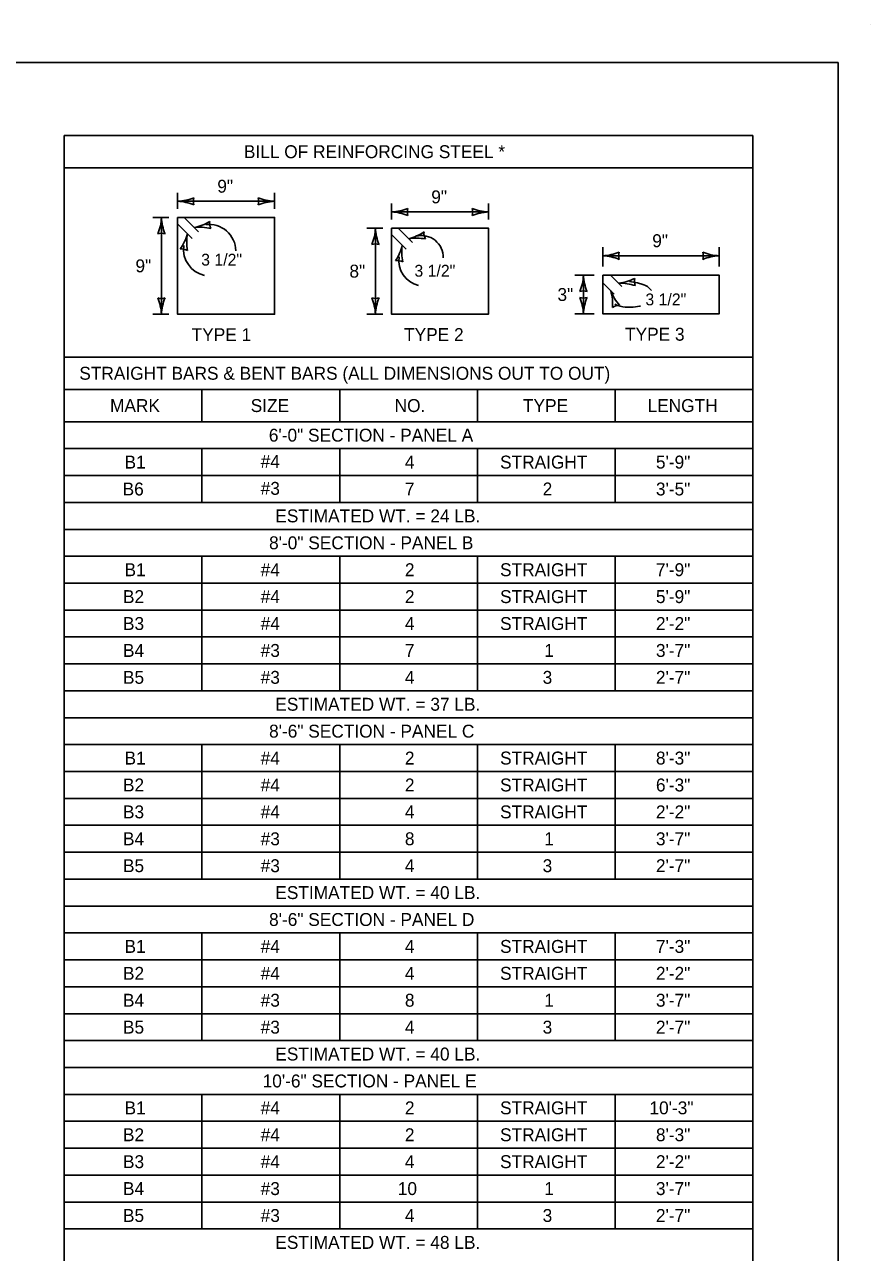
# Model space of a CAD drawing. Extents: x 49991.4 to 50021, y 49987.6 to 50011.4.
# Drawn here: x 50012.97 to 50016.9, y 49993.47 to 49999.18 of the extents above; entities that cross this region are included whole.
import ezdxf

# ---------------------------------------------------------------- set-up
doc = ezdxf.new("R2010")
doc.units = 0
for name, color, linetype in [('Level 1', 7, 'Continuous'), ('Level 2', 7, 'Continuous'), ('Level 3', 7, 'Continuous')]:
    doc.layers.add(name, color=color, linetype=linetype)

msp = doc.modelspace()

# ---------------------------------------------------------------- linework, layer by layer
at = {"layer": 'Level 1'}
for p, q in [((50016.9001, 49999.1756), (50016.9001, 49999.1756)), ((50013.713, 49998.2795), (50013.7802, 49998.2124)), ((50013.683, 49998.2495), (50013.7502, 49998.1824)), ((50014.7066, 49998.23), (50014.7738, 49998.1629)), ((50014.6766, 49998.2), (50014.7438, 49998.1329)), ((50015.6936, 49998.0114), (50015.7458, 49997.9592)), ((50015.6576, 49997.9754), (50015.7098, 49997.9232))]:
    msp.add_line(p, q, dxfattribs=at)
for points in [[(49999.3835, 49998.9992), (50016.7501, 49998.9992), (50016.7501, 49987.7988), (49999.3835, 49987.7988)], [(50013.683, 49998.2795), (50014.133, 49998.2795), (50014.133, 49997.8295), (50013.683, 49997.8295)], [(50014.6766, 49998.23), (50015.1266, 49998.23), (50015.1266, 49997.8299), (50014.6766, 49997.8299)], [(50015.6576, 49998.0114), (50016.1976, 49998.0114), (50016.1976, 49997.8314), (50015.6576, 49997.8314)]]:
    msp.add_lwpolyline(points, close=True, dxfattribs=at)
at = {"layer": 'Level 2'}
for p, q in [((50013.1565, 49998.6599), (50016.3545, 49998.6599)), ((50013.1565, 49991.0805), (50013.1565, 49998.6599)), ((50016.3545, 49991.0805), (50016.3545, 49998.6599)), ((50013.1565, 49998.5099), (50016.3545, 49998.5099)), ((50016.3545, 49997.6305), (50013.1565, 49997.6305)), ((50016.3545, 49997.4805), (50013.1565, 49997.4805)), ((50013.7961, 49997.3305), (50013.7961, 49997.4805)), ((50014.4357, 49997.3305), (50014.4357, 49997.4805)), ((50015.0753, 49997.3305), (50015.0753, 49997.4805)), ((50015.7149, 49997.3305), (50015.7149, 49997.4805)), ((50016.3545, 49997.3305), (50013.1565, 49997.3305)), ((50016.3545, 49997.2055), (50013.1565, 49997.2055)), ((50013.7961, 49996.9555), (50013.7961, 49997.2055)), ((50014.4357, 49996.9555), (50014.4357, 49997.2055)), ((50015.0753, 49996.9555), (50015.0753, 49997.2055)), ((50015.7149, 49996.9555), (50015.7149, 49997.2055)), ((50016.3545, 49997.0805), (50013.1565, 49997.0805)), ((50016.3545, 49996.9555), (50013.1565, 49996.9555)), ((50016.3545, 49996.8305), (50013.1565, 49996.8305)), ((50016.3545, 49996.7055), (50013.1565, 49996.7055)), ((50013.7961, 49996.0805), (50013.7961, 49996.7055)), ((50014.4357, 49996.0805), (50014.4357, 49996.7055)), ((50015.0753, 49996.0805), (50015.0753, 49996.7055)), ((50015.7149, 49996.0805), (50015.7149, 49996.7055)), ((50016.3545, 49996.5805), (50013.1565, 49996.5805)), ((50016.3545, 49996.4555), (50013.1565, 49996.4555)), ((50016.3545, 49996.3305), (50013.1565, 49996.3305)), ((50016.3545, 49996.2055), (50013.1565, 49996.2055)), ((50016.3545, 49996.0805), (50013.1565, 49996.0805)), ((50016.3545, 49995.9555), (50013.1565, 49995.9555)), ((50016.3545, 49995.8305), (50013.1565, 49995.8305)), ((50013.7961, 49995.2055), (50013.7961, 49995.8305)), ((50014.4357, 49995.2055), (50014.4357, 49995.8305)), ((50015.0753, 49995.2055), (50015.0753, 49995.8305)), ((50015.7149, 49995.2055), (50015.7149, 49995.8305)), ((50016.3545, 49995.7055), (50013.1565, 49995.7055)), ((50016.3545, 49995.5805), (50013.1565, 49995.5805)), ((50016.3545, 49995.4555), (50013.1565, 49995.4555)), ((50016.3545, 49995.3305), (50013.1565, 49995.3305)), ((50016.3545, 49995.2055), (50013.1565, 49995.2055)), ((50016.3545, 49995.0805), (50013.1565, 49995.0805)), ((50016.3545, 49994.9555), (50013.1565, 49994.9555)), ((50013.7961, 49994.4555), (50013.7961, 49994.9555)), ((50014.4357, 49994.4555), (50014.4357, 49994.9555)), ((50015.0753, 49994.4555), (50015.0753, 49994.9555)), ((50015.7149, 49994.4555), (50015.7149, 49994.9555)), ((50016.3545, 49994.8305), (50013.1565, 49994.8305)), ((50016.3545, 49994.7055), (50013.1565, 49994.7055)), ((50016.3545, 49994.5805), (50013.1565, 49994.5805)), ((50016.3545, 49994.4555), (50013.1565, 49994.4555)), ((50016.3545, 49994.3305), (50013.1565, 49994.3305)), ((50016.3545, 49994.2055), (50013.1565, 49994.2055)), ((50013.7961, 49993.5805), (50013.7961, 49994.2055)), ((50014.4357, 49993.5805), (50014.4357, 49994.2055)), ((50015.0753, 49993.5805), (50015.0753, 49994.2055)), ((50015.7149, 49993.5805), (50015.7149, 49994.2055)), ((50016.3545, 49994.0805), (50013.1565, 49994.0805)), ((50016.3545, 49993.9555), (50013.1565, 49993.9555)), ((50016.3545, 49993.8305), (50013.1565, 49993.8305)), ((50016.3545, 49993.7055), (50013.1565, 49993.7055)), ((50016.3545, 49993.5805), (50013.1565, 49993.5805))]:
    msp.add_line(p, q, dxfattribs=at)
at = {"layer": 'Level 3'}
for p, q in [((50013.683, 49998.3195), (50013.683, 49998.3945)), ((50014.133, 49998.3195), (50014.133, 49998.3945)), ((50013.683, 49998.3545), (50014.133, 49998.3545)), ((50014.6766, 49998.27), (50014.6766, 49998.345)), ((50015.1266, 49998.27), (50015.1266, 49998.345)), ((50013.643, 49998.2795), (50013.568, 49998.2795)), ((50013.608, 49997.8295), (50013.608, 49998.2795)), ((50014.6766, 49998.305), (50015.1266, 49998.305)), ((50014.6366, 49998.23), (50014.5616, 49998.23)), ((50014.6016, 49997.8299), (50014.6016, 49998.23)), ((50015.6576, 49998.0514), (50015.6576, 49998.1414)), ((50015.6576, 49998.1014), (50016.1976, 49998.1014)), ((50016.1976, 49998.0514), (50016.1976, 49998.1414)), ((50015.6176, 49998.0114), (50015.5275, 49998.0114)), ((50015.5675, 49997.8314), (50015.5675, 49998.0114)), ((50013.643, 49997.8295), (50013.568, 49997.8295)), ((50014.6366, 49997.8299), (50014.5616, 49997.8299)), ((50015.6176, 49997.8314), (50015.5275, 49997.8314))]:
    msp.add_line(p, q, dxfattribs=at)
for centre, radius, start, end in [((50013.6715, 49998.5872), 0.233, 272.8273, 292.0772), ((50013.6738, 49998.1324), 0.2223, 67.456, 87.6395), ((50013.8112, 49998.3545), 0.0548, 162.1388, 197.8612), ((50014.1422, 49998.5766), 0.2223, 247.456, 267.6395), ((50014.0048, 49998.3545), 0.0548, 342.1388, 17.8612), ((50014.1445, 49998.1218), 0.233, 92.8273, 112.0772), ((50013.3859, 49998.2887), 0.2223, 337.456, 357.6395), ((50013.8407, 49998.291), 0.233, 182.8273, 202.0772), ((50014.6651, 49998.5377), 0.233, 272.8273, 292.0772), ((50014.6674, 49998.0829), 0.2223, 67.456, 87.6395), ((50014.8048, 49998.305), 0.0548, 162.1388, 197.8612), ((50015.1358, 49998.5271), 0.2223, 247.456, 267.6395), ((50014.9984, 49998.305), 0.0548, 342.1388, 17.8612), ((50015.1381, 49998.0723), 0.233, 92.8273, 112.0772), ((50013.7131, 49998.461), 0.233, 281.5629, 300.8128), ((50013.7845, 49998.0118), 0.2223, 76.1916, 96.3752), ((50013.8294, 49998.1235), 0.1237, 0.6372, 97.4281), ((50013.8865, 49998.2522), 0.0548, 170.8745, 206.5968), ((50014.3795, 49998.2392), 0.2223, 337.456, 357.6395), ((50014.8343, 49998.2415), 0.233, 182.8273, 202.0772), ((50014.6973, 49998.4059), 0.233, 284.6402, 303.8901), ((50014.8817, 49998.2068), 0.0548, 173.9517, 209.6741), ((50013.608, 49998.1513), 0.0548, 72.1388, 107.8612), ((50013.514, 49998.2616), 0.2223, 324.7688, 344.9523), ((50013.9582, 49998.164), 0.233, 170.1401, 189.39), ((50014.6016, 49998.1018), 0.0548, 72.1388, 107.8612), ((50014.7927, 49997.9612), 0.2223, 79.2689, 99.4524), ((50014.8157, 49998.0947), 0.1007, 358.0024, 104.4981), ((50013.7005, 49998.0788), 0.0548, 59.4516, 95.174), ((50013.8351, 49998.1315), 0.1245, 172.119, 257.5679), ((50014.5094, 49998.2007), 0.2223, 326.8049, 346.9884), ((50014.828, 49998.0787), 0.1178, 171.5129, 257.0556), ((50014.9569, 49998.1189), 0.233, 172.1762, 191.426), ((50015.6461, 49998.3341), 0.233, 272.8273, 292.0772), ((50015.6484, 49997.8793), 0.2223, 67.456, 87.6395), ((50015.7858, 49998.1014), 0.0548, 162.1388, 197.8612), ((50016.2068, 49998.3235), 0.2223, 247.456, 267.6395), ((50016.0694, 49998.1014), 0.0548, 342.1388, 17.8612), ((50016.2091, 49997.8687), 0.233, 92.8273, 112.0772), ((50014.7023, 49998.0246), 0.0548, 61.4877, 97.21), ((50015.3454, 49998.0206), 0.2223, 337.456, 357.6395), ((50015.8002, 49998.0229), 0.233, 182.8273, 202.0772), ((50015.7022, 49998.205), 0.233, 277.1537, 296.4036), ((50015.8591, 49997.9835), 0.0548, 166.4652, 202.1876), ((50015.5675, 49997.8832), 0.0548, 72.1388, 107.8612), ((50015.4807, 49997.8772), 0.2223, 355.8418, 16.0253), ((50015.9116, 49998.0229), 0.233, 201.2131, 220.4629), ((50015.7388, 49997.7516), 0.2223, 71.7824, 91.9659), ((50013.608, 49997.9577), 0.0548, 252.1388, 287.8612), ((50013.3753, 49997.818), 0.233, 2.8273, 22.0772), ((50013.8301, 49997.8203), 0.2223, 157.456, 177.6395), ((50014.6016, 49997.9581), 0.0548, 252.1388, 287.8612), ((50014.3689, 49997.8184), 0.233, 2.8273, 22.0772), ((50014.8237, 49997.8207), 0.2223, 157.456, 177.6395), ((50015.5675, 49997.9596), 0.0548, 252.1388, 287.8612), ((50015.3348, 49997.8199), 0.233, 2.8273, 22.0772), ((50015.7896, 49997.8222), 0.2223, 157.456, 177.6395), ((50015.7348, 49997.8169), 0.0548, 90.5246, 126.2469)]:
    msp.add_arc(centre, radius, start, end, dxfattribs=at)
for points in [[(50015.7818, 49997.9817), (50015.8184, 49997.9752), (50015.8382, 49997.9699), (50015.8719, 49997.9524), (50015.8833, 49997.9402)], [(50015.7133, 49997.8762), (50015.7267, 49997.8709), (50015.7511, 49997.8648), (50015.8275, 49997.8671), (50015.8324, 49997.8684)]]:
    msp.add_spline(points, degree=3, dxfattribs=at)

# ---------------------------------------------------------------- texts
at = {"layer": 'Level 2'}
for s, height, p in [('BILL OF REINFORCING STEEL *', 0.06, (50013.9909, 49998.5549)), ('9"', 0.06, (50013.8674, 49998.3945)), ('9"', 0.06, (50014.861, 49998.345)), ('9"', 0.06, (50015.887, 49998.1414)), ('3 1/2"', 0.055, (50013.7925, 49998.0558)), ('9"', 0.06, (50013.4873, 49998.0245)), ('8"', 0.06, (50014.4809, 49998)), ('3 1/2"', 0.055, (50014.7827, 49998.0044)), ('3"', 0.06, (50015.4468, 49997.8914)), ('3 1/2"', 0.055, (50015.8552, 49997.8712)), ('TYPE 1', 0.06, (50013.7483, 49997.705)), ('TYPE 2', 0.06, (50014.7347, 49997.7054)), ('TYPE 3', 0.06, (50015.7607, 49997.7069)), ('STRAIGHT BARS & BENT BARS (ALL DIMENSIONS OUT TO OUT)', 0.06, (50013.2267, 49997.5255)), ('MARK', 0.06, (50013.3693, 49997.3755)), ('SIZE', 0.06, (50014.0224, 49997.3755)), ('NO.', 0.06, (50014.6907, 49997.3755)), ('TYPE', 0.06, (50015.2867, 49997.3755)), ('LENGTH', 0.06, (50015.8651, 49997.3755)), ('6\'-0" SECTION - PANEL A', 0.06, (50014.1067, 49997.238)), ('B1', 0.06, (50013.4367, 49997.113)), ('#4', 0.06, (50014.0689, 49997.116)), ('4', 0.06, (50014.7385, 49997.113)), ('STRAIGHT', 0.06, (50015.1804, 49997.113)), ('5\'-9"', 0.06, (50015.9041, 49997.113)), ('B6', 0.06, (50013.4277, 49996.988)), ('#3', 0.06, (50014.0689, 49996.991)), ('7', 0.06, (50014.7385, 49996.988)), ('2', 0.06, (50015.3781, 49996.988)), ('3\'-5"', 0.06, (50015.9041, 49996.988)), ('ESTIMATED WT. = 24 LB.', 0.06, (50014.1367, 49996.863)), ('8\'-0" SECTION - PANEL B', 0.06, (50014.1077, 49996.738)), ('B1', 0.06, (50013.4367, 49996.613)), ('#4', 0.06, (50014.0689, 49996.613)), ('2', 0.06, (50014.7385, 49996.613)), ('STRAIGHT', 0.06, (50015.1804, 49996.613)), ('7\'-9"', 0.06, (50015.9041, 49996.613)), ('B2', 0.06, (50013.4293, 49996.488)), ('#4', 0.06, (50014.0689, 49996.488)), ('2', 0.06, (50014.7385, 49996.488)), ('STRAIGHT', 0.06, (50015.1804, 49996.488)), ('5\'-9"', 0.06, (50015.9041, 49996.488)), ('B3', 0.06, (50013.4293, 49996.363)), ('#4', 0.06, (50014.0689, 49996.363)), ('4', 0.06, (50014.7385, 49996.363)), ('STRAIGHT', 0.06, (50015.1804, 49996.363)), ('2\'-2"', 0.06, (50015.9041, 49996.363)), ('B4', 0.06, (50013.4293, 49996.238)), ('#3', 0.06, (50014.0689, 49996.238)), ('7', 0.06, (50014.7385, 49996.238)), ('1', 0.06, (50015.3855, 49996.238)), ('3\'-7"', 0.06, (50015.9041, 49996.238)), ('B5', 0.06, (50013.4293, 49996.113)), ('#3', 0.06, (50014.0689, 49996.113)), ('4', 0.06, (50014.7385, 49996.113)), ('3', 0.06, (50015.3781, 49996.113)), ('2\'-7"', 0.06, (50015.9041, 49996.113)), ('ESTIMATED WT. = 37 LB.', 0.06, (50014.1367, 49995.988)), ('8\'-6" SECTION - PANEL C', 0.06, (50014.1077, 49995.863)), ('B1', 0.06, (50013.4367, 49995.738)), ('#4', 0.06, (50014.0689, 49995.738)), ('2', 0.06, (50014.7385, 49995.738)), ('STRAIGHT', 0.06, (50015.1804, 49995.738)), ('8\'-3"', 0.06, (50015.9041, 49995.738)), ('B2', 0.06, (50013.4293, 49995.613)), ('#4', 0.06, (50014.0689, 49995.613)), ('2', 0.06, (50014.7385, 49995.613)), ('STRAIGHT', 0.06, (50015.1804, 49995.613)), ('6\'-3"', 0.06, (50015.9041, 49995.613)), ('B3', 0.06, (50013.4293, 49995.488)), ('#4', 0.06, (50014.0689, 49995.488)), ('4', 0.06, (50014.7385, 49995.488)), ('STRAIGHT', 0.06, (50015.1804, 49995.488)), ('2\'-2"', 0.06, (50015.9041, 49995.488)), ('B4', 0.06, (50013.4293, 49995.363)), ('#3', 0.06, (50014.0689, 49995.363)), ('8', 0.06, (50014.7385, 49995.363)), ('1', 0.06, (50015.3855, 49995.363)), ('3\'-7"', 0.06, (50015.9041, 49995.363)), ('B5', 0.06, (50013.4293, 49995.238)), ('#3', 0.06, (50014.0689, 49995.238)), ('4', 0.06, (50014.7385, 49995.238)), ('3', 0.06, (50015.3781, 49995.238)), ('2\'-7"', 0.06, (50015.9041, 49995.238)), ('ESTIMATED WT. = 40 LB.', 0.06, (50014.1367, 49995.113)), ('8\'-6" SECTION - PANEL D', 0.06, (50014.1077, 49994.988)), ('B1', 0.06, (50013.4367, 49994.863)), ('#4', 0.06, (50014.0689, 49994.863)), ('4', 0.06, (50014.7385, 49994.863)), ('STRAIGHT', 0.06, (50015.1804, 49994.863)), ('7\'-3"', 0.06, (50015.9041, 49994.863)), ('B2', 0.06, (50013.4293, 49994.738)), ('#4', 0.06, (50014.0689, 49994.738)), ('4', 0.06, (50014.7385, 49994.738)), ('STRAIGHT', 0.06, (50015.1804, 49994.738)), ('2\'-2"', 0.06, (50015.9041, 49994.738)), ('B4', 0.06, (50013.4293, 49994.613)), ('#3', 0.06, (50014.0689, 49994.613)), ('8', 0.06, (50014.7385, 49994.613)), ('1', 0.06, (50015.3855, 49994.613)), ('3\'-7"', 0.06, (50015.9041, 49994.613)), ('B5', 0.06, (50013.4293, 49994.488)), ('#3', 0.06, (50014.0689, 49994.488)), ('4', 0.06, (50014.7385, 49994.488)), ('3', 0.06, (50015.3781, 49994.488)), ('2\'-7"', 0.06, (50015.9041, 49994.488)), ('ESTIMATED WT. = 40 LB.', 0.06, (50014.1367, 49994.363)), ('10\'-6" SECTION - PANEL E', 0.06, (50014.0779, 49994.238)), ('B1', 0.06, (50013.4367, 49994.113)), ('#4', 0.06, (50014.0689, 49994.113)), ('2', 0.06, (50014.7385, 49994.113)), ('STRAIGHT', 0.06, (50015.1804, 49994.113)), ('10\'-3"', 0.06, (50015.8741, 49994.113)), ('B2', 0.06, (50013.4293, 49993.988)), ('#4', 0.06, (50014.0689, 49993.988)), ('2', 0.06, (50014.7385, 49993.988)), ('STRAIGHT', 0.06, (50015.1804, 49993.988)), ('8\'-3"', 0.06, (50015.9041, 49993.988)), ('B3', 0.06, (50013.4293, 49993.863)), ('#4', 0.06, (50014.0689, 49993.863)), ('4', 0.06, (50014.7385, 49993.863)), ('STRAIGHT', 0.06, (50015.1804, 49993.863)), ('2\'-2"', 0.06, (50015.9041, 49993.863)), ('B4', 0.06, (50013.4293, 49993.738)), ('#3', 0.06, (50014.0689, 49993.738)), ('10', 0.06, (50014.7055, 49993.738)), ('1', 0.06, (50015.3855, 49993.738)), ('3\'-7"', 0.06, (50015.9041, 49993.738)), ('B5', 0.06, (50013.4293, 49993.613)), ('#3', 0.06, (50014.0689, 49993.613)), ('4', 0.06, (50014.7385, 49993.613)), ('3', 0.06, (50015.3781, 49993.613)), ('2\'-7"', 0.06, (50015.9041, 49993.613)), ('ESTIMATED WT. = 48 LB.', 0.06, (50014.1367, 49993.488))]:
    msp.add_text(s, height=height, dxfattribs=at).set_placement(p)

doc.saveas('drawing.dxf')
